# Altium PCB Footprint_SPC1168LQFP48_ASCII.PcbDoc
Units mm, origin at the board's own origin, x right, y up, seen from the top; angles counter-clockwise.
Board outline 152.4 x 101.6 mm, 2 copper layers (Top Layer, Bottom Layer); 1 components, 0 nets, 48 pads, 0 vias.
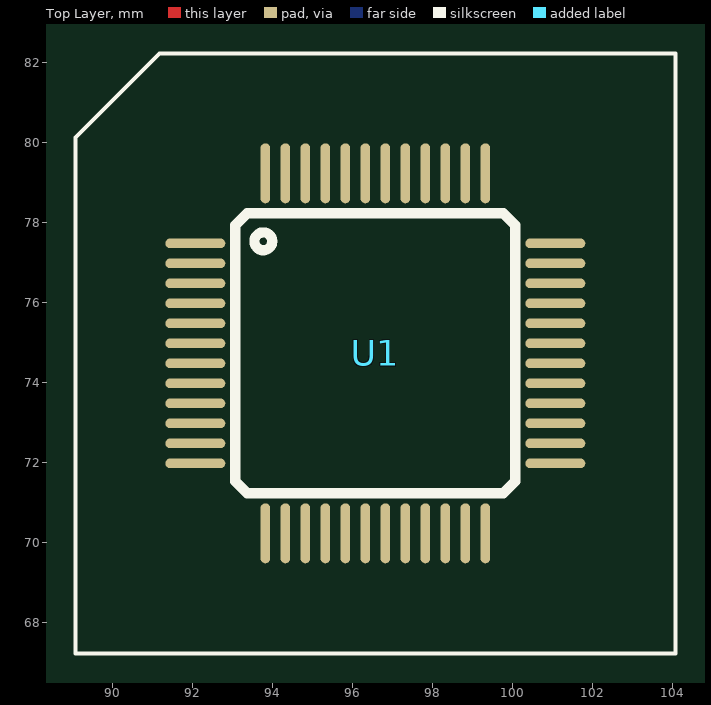
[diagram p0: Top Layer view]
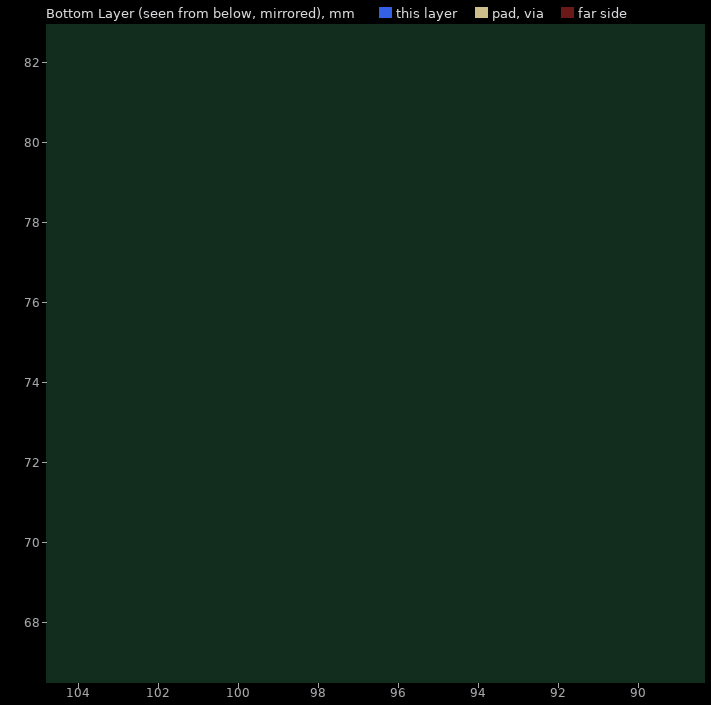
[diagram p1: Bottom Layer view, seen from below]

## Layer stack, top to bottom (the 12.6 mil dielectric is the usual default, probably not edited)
Top Solder: solder mask 0.0102, Solder Resist, Dk 3.5
Top Layer: signal copper 0.0356
Dielectric 1: dielectric 0.32, FR-4, Dk 4.8
Bottom Layer: signal copper 0.0356
Bottom Solder: solder mask 0.0102, Solder Resist, Dk 3.5

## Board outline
25.4,25.4 177.8,25.4 177.8,127 25.4,127

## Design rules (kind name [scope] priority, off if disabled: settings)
AssemblyTestPointUsage [All] p0: scope1count=1 scope1_0_kind=Board scope1_0_value=Board scope2count=1 scope2_0_kind=Board scope2_0_value=Board commentlength=0
AssemblyTestpoint [All] p0: scope1count=1 scope1_0_kind=Board scope1_0_value=Board scope2count=1 scope2_0_kind=Board scope2_0_value=Board commentlength=0
Clearance [All] p0: scope1count=1 scope1_0_kind=Board scope1_0_value=Board scope2count=1 scope2_0_kind=Board scope2_0_value=Board commentlength=0 gap=0.254
Clearance [All] p1: gap=0.254 ignorepadtopadclearanceinfootprint=FALSE except(0: Arc-Hole Track-Hole SMDPad-Hole THPad-Hole Via-Hole Fill-Hole Poly-Hole Region-Hole Text-Hole)
ComponentClearance [All] p0: scope1count=1 scope1_0_kind=Board scope1_0_value=Board scope2count=1 scope2_0_kind=Board scope2_0_value=Board commentlength=0 gap=0.254 collisioncheckmode=3
DiffPairsRouting [All] p0: scope1count=1 scope1_0_kind=Board scope1_0_value=Board scope2count=1 scope2_0_kind=Board scope2_0_value=Board commentlength=0
FabricationTestPointUsage [All] p0: scope1count=1 scope1_0_kind=Board scope1_0_value=Board scope2count=1 scope2_0_kind=Board scope2_0_value=Board commentlength=0 valid=0 allowmultiple=FALSE
FabricationTestpoint [All] p0: scope1count=1 scope1_0_kind=Board scope1_0_value=Board scope2count=1 scope2_0_kind=Board scope2_0_value=Board commentlength=0 side=3 testpointundercomponent=TRUE minsize=1.016 maxsize=2.54 preferedsize=1.524 minholesize=0 maxholesize=1.016 preferedholesize=0.813 testpointgrid=0.025
FanoutControl Fanout_BGA [All] p0 off: scope1count=1 scope1_0_kind=Board scope1_0_value=Board scope2count=1 scope2_0_kind=Board scope2_0_value=Board commentlength=69 // Protel DXP Scope 1 Expression Was: IsBGA   Fanout_BGA (Default Rule)
FanoutControl Fanout_LCC [All] p0 off: scope1count=1 scope1_0_kind=Board scope1_0_value=Board scope2count=1 scope2_0_kind=Board scope2_0_value=Board commentlength=69 // Protel DXP Scope 1 Expression Was: IsLCC   Fanout_LCC (Default Rule)
FanoutControl Fanout_SOIC [All] p0 off: scope1count=1 scope1_0_kind=Board scope1_0_value=Board scope2count=1 scope2_0_kind=Board scope2_0_value=Board commentlength=71 // Protel DXP Scope 1 Expression Was: IsSOIC   Fanout_SOIC (Default Rule)
FanoutControl Fanout_Small [All] p0 off: scope1count=1 scope1_0_kind=Board scope1_0_value=Board scope2count=1 scope2_0_kind=Board scope2_0_value=Board commentlength=84 // Protel DXP Scope 1 Expression Was: (CompPinCount < 5)   Fanout_Small (Default Rule)
FanoutControl Fanout_Default [All] p0: scope1count=1 scope1_0_kind=Board scope1_0_value=Board scope2count=1 scope2_0_kind=Board scope2_0_value=Board commentlength=30 // Fanout_Default (Default Rule)
Height [All] p0: scope1count=1 scope1_0_kind=Board scope1_0_value=Board scope2count=1 scope2_0_kind=Board scope2_0_value=Board commentlength=0
HoleSize [All] p0: scope1count=1 scope1_0_kind=Board scope1_0_value=Board scope2count=1 scope2_0_kind=Board scope2_0_value=Board commentlength=0 absolutevalues=TRUE maxlimit=2.54 minlimit=0.025 maxpercent=80.000 minpercent=20.000
HoleToHoleClearance [All] p0: scope1count=1 scope1_0_kind=Board scope1_0_value=Board scope2count=1 scope2_0_kind=Board scope2_0_value=Board commentlength=0
LayerPairs [All] p0: scope1count=1 scope1_0_kind=Board scope1_0_value=Board scope2count=1 scope2_0_kind=Board scope2_0_value=Board commentlength=0 enforce=TRUE
MinimumSolderMaskSliver [All] p0: scope1count=1 scope1_0_kind=Board scope1_0_value=Board scope2count=1 scope2_0_kind=Board scope2_0_value=Board commentlength=0
NetAntennae [All] p0: scope1count=1 scope1_0_kind=Board scope1_0_value=Board scope2count=1 scope2_0_kind=Board scope2_0_value=Board commentlength=0
PasteMaskExpansion [All] p0: scope1count=1 scope1_0_kind=Board scope1_0_value=Board scope2count=1 scope2_0_kind=Board scope2_0_value=Board commentlength=0 expansion=0
PlaneClearance [All] p0: scope1count=1 scope1_0_kind=Board scope1_0_value=Board scope2count=1 scope2_0_kind=Board scope2_0_value=Board commentlength=0 clearance=0.508
PlaneConnect [All] p0: scope1count=1 scope1_0_kind=Board scope1_0_value=Board scope2count=1 scope2_0_kind=Board scope2_0_value=Board commentlength=0 planeconnectstyle=Relief reliefexpansion=0.508 reliefentries=4 reliefconductorwidth=0.254 reliefairgap=0.254
PolygonConnect [All] p0: scope1count=1 scope1_0_kind=Board scope1_0_value=Board scope2count=1 scope2_0_kind=Board scope2_0_value=Board commentlength=0 connectstyle=Relief reliefconductorwidth=0.254 reliefentries=4 polygonreliefangle="90 Angle"
PolygonConnect [All] p1: connectstyle=Relief reliefconductorwidth=0.254 reliefentries=4 polygonreliefangle="90 Angle" airgapwidth=0.254
RoutingCorners [All] p0: scope1count=1 scope1_0_kind=Board scope1_0_value=Board scope2count=1 scope2_0_kind=Board scope2_0_value=Board commentlength=0 cornerstyle=45-Degree minsetback=2.54 maxsetback=2.54
RoutingLayers [All] p0: scope1count=1 scope1_0_kind=Board scope1_0_value=Board scope2count=1 scope2_0_kind=Board scope2_0_value=Board commentlength=0 top layer=Automatic bottom layer=Automatic
RoutingPriority [All] p0: scope1count=1 scope1_0_kind=Board scope1_0_value=Board scope2count=1 scope2_0_kind=Board scope2_0_value=Board commentlength=0
RoutingTopology [All] p0: scope1count=1 scope1_0_kind=Board scope1_0_value=Board scope2count=1 scope2_0_kind=Board scope2_0_value=Board commentlength=0 topology=Shortest
RoutingVias [All] p0: scope1count=1 scope1_0_kind=Board scope1_0_value=Board scope2count=1 scope2_0_kind=Board scope2_0_value=Board commentlength=0 holewidth=0.711 width=1.27 viastyle="Through Hole" minholewidth=0.711 minwidth=1.27 maxholewidth=0.711 maxwidth=1.27
RoutingVias [All] p1: holewidth=0.711 width=1.27 viastyle="Through Hole" minholewidth=0.711 minwidth=1.27 maxholewidth=0.711 maxwidth=1.27
ShortCircuit [All] p0: scope1count=1 scope1_0_kind=Board scope1_0_value=Board scope2count=1 scope2_0_kind=Board scope2_0_value=Board commentlength=0 allowed=FALSE
SilkToBoardRegionClearance [All] p0: scope1count=1 scope1_0_kind=Board scope1_0_value=Board scope2count=1 scope2_0_kind=Board scope2_0_value=Board commentlength=0
SilkToSilkClearance [All] p0: scope1count=1 scope1_0_kind=Board scope1_0_value=Board scope2count=1 scope2_0_kind=Board scope2_0_value=Board commentlength=0
SilkToSolderMaskClearance [All] p0 off: scope1count=1 scope1_0_kind=Board scope1_0_value=Board scope2count=1 scope2_0_kind=Board scope2_0_value=Board commentlength=44 // Protel DXP Scope 1 Expression Was: IsPad
SolderMaskExpansion [All] p0: scope1count=1 scope1_0_kind=Board scope1_0_value=Board scope2count=1 scope2_0_kind=Board scope2_0_value=Board commentlength=0 expansion=0.102
SolderMaskExpansion [All] p1: expansion=0.102 istentingtop=FALSE
UnRoutedNet [All] p0: scope1count=1 scope1_0_kind=Board scope1_0_value=Board scope2count=1 scope2_0_kind=Board scope2_0_value=Board commentlength=0
UnpouredPolygon [All] p0: scope1count=1 scope1_0_kind=Board scope1_0_value=Board scope2count=1 scope2_0_kind=Board scope2_0_value=Board commentlength=0
Width [All] p0: scope1count=1 scope1_0_kind=Board scope1_0_value=Board scope2count=1 scope2_0_kind=Board scope2_0_value=Board commentlength=0 maxlimit=0.254 minlimit=0.254 preferedwidth=0.254
Width [All] p1: maxlimit=0.254 minlimit=0.254 preferedwidth=0.254
30 further rules are at their usual default settings.

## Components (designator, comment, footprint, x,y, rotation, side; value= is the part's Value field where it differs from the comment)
U1 "" PQFP48 96.575,74.72 r0 top

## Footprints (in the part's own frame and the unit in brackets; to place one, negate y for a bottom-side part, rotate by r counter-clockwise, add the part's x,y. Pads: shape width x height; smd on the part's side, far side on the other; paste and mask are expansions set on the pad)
PQFP48 [mm]
  oval 1.5x0.24 smd: 1(-4.5,2.75) 2(-4.5,2.25) 3(-4.5,1.75) 4(-4.5,1.25) 5(-4.5,0.75) 6(-4.5,0.25) 7(-4.5,-0.25) 8(-4.5,-0.75) 9(-4.5,-1.25) 10(-4.5,-1.75) 11(-4.5,-2.25) 12(-4.5,-2.75) 25(4.5,-2.75) 26(4.5,-2.25) 27(4.5,-1.75) 28(4.5,-1.25) 29(4.5,-0.75) 30(4.5,-0.25) 31(4.5,0.25) 32(4.5,0.75) 33(4.5,1.25) 34(4.5,1.75) 35(4.5,2.25) 36(4.5,2.75)
  oval 0.24x1.5 smd: 13(-2.75,-4.5) 14(-2.25,-4.5) 15(-1.75,-4.5) 16(-1.25,-4.5) 17(-0.75,-4.5) 18(-0.25,-4.5) 19(0.25,-4.5) 20(0.75,-4.5) 21(1.25,-4.5) 22(1.75,-4.5) 23(2.25,-4.5) 24(2.75,-4.5) 37(2.75,4.5) 38(2.25,4.5) 39(1.75,4.5) 40(1.25,4.5) 41(0.75,4.5) 42(0.25,4.5) 43(-0.25,4.5) 44(-0.75,4.5) 45(-1.25,4.5) 46(-1.75,4.5) 47(-2.25,4.5) 48(-2.75,4.5)
  silkscreen extent -7.5,-7.5 7.5,7.5

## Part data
U1: library part GECKO, "32-bit ARM CM4 MCU"

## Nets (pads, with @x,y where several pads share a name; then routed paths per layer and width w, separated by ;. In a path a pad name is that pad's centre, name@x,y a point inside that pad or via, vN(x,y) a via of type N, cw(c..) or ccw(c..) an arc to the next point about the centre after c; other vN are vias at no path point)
pads on no net: U1.1 U1.2 U1.3 U1.4 U1.5 U1.6 U1.7 U1.8 U1.9 U1.10 U1.11 U1.12 U1.13 U1.14 U1.15 U1.16 U1.17 U1.18 U1.19 U1.20 U1.21 U1.22 U1.23 U1.24 U1.25 U1.26 U1.27 U1.28 U1.29 U1.30 U1.31 U1.32 U1.33 U1.34 U1.35 U1.36 U1.37 U1.38 U1.39 U1.40 U1.41 U1.42 U1.43 U1.44 U1.45 U1.46 U1.47 U1.48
